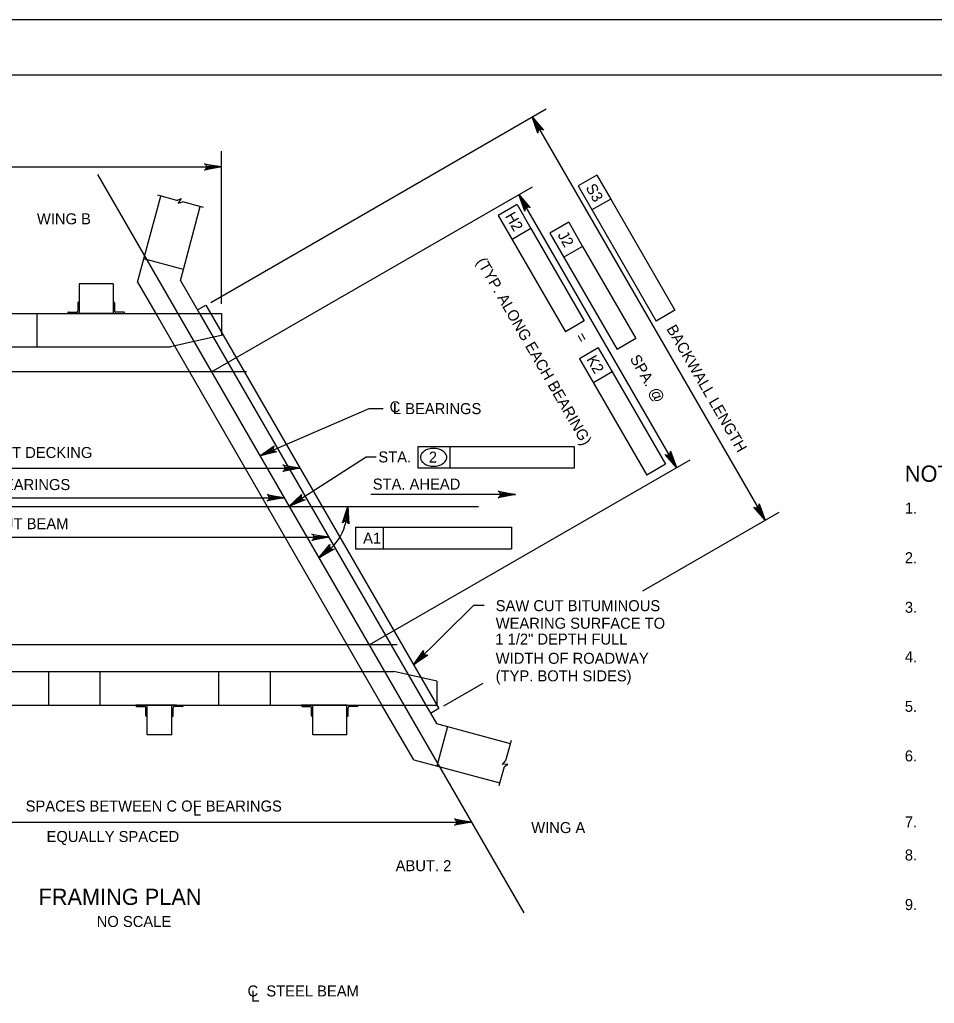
# Model space of a CAD drawing. Extents: x 638175 to 640495, y 294277 to 298435.
# Drawn here: x 639605.4 to 639854.5, y 298167.4 to 298435.5 of the extents above; entities that cross this region are included whole.
import ezdxf

# ---------------------------------------------------------------- set-up
doc = ezdxf.new("R2010")
doc.units = 0
for name, color, linetype in [('2', 7, 'Continuous'), ('3', 7, 'Continuous'), ('4', 7, 'Continuous'), ('PLT-BNDY', 7, 'Continuous')]:
    doc.layers.add(name, color=color, linetype=linetype)

msp = doc.modelspace()

# ---------------------------------------------------------------- linework, layer by layer
at = {"layer": '2'}
for p, q in [((639316.46, 298420.46), (640102.46, 298420.46)), ((639637.52, 298363.97), (639643.8, 298387.4)), ((639650.02, 298367.43), (639654.59, 298384.51)), ((639650.02, 298367.43), (639639.22, 298370.32)), ((639649.21, 298364.4), (639650.02, 298367.43)), ((639649.21, 298364.4), (639654.39, 298355.43)), ((639630.84, 298363.52), (639621.6, 298363.52)), ((639621.6, 298363.52), (639621.6, 298355.43)), ((639630.84, 298363.52), (639630.84, 298355.43)), ((639637.52, 298363.97), (639642.46, 298355.43)), ((639621.24, 298358.34), (639621.24, 298356.15)), ((639621.42, 298358.52), (639621.6, 298358.52)), ((639621.6, 298358.52), (639621.6, 298355.43)), ((639631.02, 298358.52), (639630.84, 298358.52)), ((639630.84, 298358.52), (639630.84, 298355.43)), ((639631.2, 298358.34), (639631.2, 298356.15)), ((639653.84, 298356.38), (639656.08, 298357.67)), ((639656.08, 298357.67), (639719.54, 298247.75)), ((639455.72, 298355.43), (639660.35, 298355.43)), ((639610.05, 298355.43), (639610.05, 298346.31)), ((639618.51, 298355.61), (639618.51, 298355.43)), ((639621.6, 298355.43), (639618.51, 298355.43)), ((639618.69, 298355.79), (639620.87, 298355.79)), ((639630.84, 298355.43), (639621.6, 298355.43)), ((639630.84, 298355.43), (639633.93, 298355.43)), ((639633.75, 298355.79), (639631.56, 298355.79)), ((639633.93, 298355.61), (639633.93, 298355.43)), ((639642.46, 298355.43), (639704.07, 298248.7)), ((639654.39, 298355.43), (639716.01, 298248.7)), ((639660.35, 298355.43), (639660.35, 298349.4)), ((639658.17, 298348.91), (639646.49, 298346.31)), ((639660.34, 298349.4), (639658.17, 298348.91)), ((639469.57, 298346.31), (639646.49, 298346.31)), ((639561.51, 298257.82), (639707.31, 298257.82)), ((639613.3, 298248.7), (639613.3, 298257.82)), ((639627.32, 298248.7), (639627.32, 298257.82)), ((639659.66, 298248.7), (639659.66, 298257.82)), ((639673.68, 298248.7), (639673.68, 298257.82)), ((639718.99, 298255.22), (639707.31, 298257.82)), ((639718.99, 298255.22), (639718.99, 298248.7)), ((639514.35, 298248.7), (639718.99, 298248.7)), ((639637.04, 298248.52), (639637.04, 298248.7)), ((639640.13, 298248.7), (639637.04, 298248.7)), ((639637.22, 298248.34), (639639.4, 298248.34)), ((639648.11, 298248.7), (639638.87, 298248.7)), ((639639.76, 298245.79), (639639.76, 298247.97)), ((639646.85, 298248.7), (639640.13, 298248.7)), ((639640.13, 298245.61), (639640.13, 298248.7)), ((639640.13, 298240.61), (639640.13, 298248.7)), ((639646.85, 298245.61), (639646.85, 298248.7)), ((639646.85, 298248.7), (639649.94, 298248.7)), ((639646.85, 298240.61), (639646.85, 298248.7)), ((639647.22, 298245.79), (639647.22, 298247.97)), ((639649.76, 298248.34), (639647.58, 298248.34)), ((639649.94, 298248.52), (639649.94, 298248.7)), ((639682.14, 298248.52), (639682.14, 298248.7)), ((639685.24, 298248.7), (639682.14, 298248.7)), ((639682.33, 298248.34), (639684.51, 298248.34)), ((639684.87, 298245.79), (639684.87, 298247.97)), ((639694.47, 298248.7), (639685.24, 298248.7)), ((639685.24, 298245.61), (639685.24, 298248.7)), ((639685.24, 298240.61), (639685.24, 298248.7)), ((639694.47, 298245.61), (639694.47, 298248.7)), ((639694.47, 298248.7), (639697.56, 298248.7)), ((639694.47, 298240.61), (639694.47, 298248.7)), ((639694.84, 298245.79), (639694.84, 298247.97)), ((639697.38, 298248.34), (639695.2, 298248.34)), ((639697.56, 298248.52), (639697.56, 298248.7)), ((639712.7, 298233.75), (639704.07, 298248.7)), ((639716.01, 298248.7), (639718.92, 298243.66)), ((639719.54, 298247.75), (639717.3, 298246.45)), ((639639.94, 298245.61), (639640.13, 298245.61)), ((639647.04, 298245.61), (639646.85, 298245.61)), ((639685.05, 298245.61), (639685.24, 298245.61)), ((639694.65, 298245.61), (639694.47, 298245.61)), ((639718.92, 298243.66), (639721.94, 298242.85)), ((639721.94, 298242.85), (639719.05, 298232.05)), ((639721.94, 298242.85), (639739.02, 298238.27)), ((639646.85, 298240.61), (639640.13, 298240.61)), ((639694.47, 298240.61), (639685.24, 298240.61)), ((639712.7, 298233.75), (639736.13, 298227.48))]:
    msp.add_line(p, q, dxfattribs=at)
for centre, radius, start, end in [((639621.42, 298358.34), 0.182, 90, 179.9984), ((639631.02, 298358.34), 0.182, 0.0016, 90), ((639618.69, 298355.61), 0.182, 90, 179.9984), ((639620.87, 298356.15), 0.364, 270, 359.9984), ((639631.56, 298356.15), 0.364, 180.0016, 270), ((639633.75, 298355.61), 0.182, 0.0016, 90), ((639637.22, 298248.52), 0.182, 180.0016, 270), ((639639.4, 298247.97), 0.364, 0.0016, 90), ((639647.58, 298247.97), 0.364, 90, 179.9984), ((639649.76, 298248.52), 0.182, 270, 359.9984), ((639682.33, 298248.52), 0.182, 180.0016, 270), ((639684.51, 298247.97), 0.364, 0.0016, 90), ((639695.2, 298247.97), 0.364, 90, 179.9984), ((639697.38, 298248.52), 0.182, 270, 359.9984), ((639639.94, 298245.79), 0.182, 180.0016, 270), ((639647.04, 298245.79), 0.182, 270, 359.9984), ((639685.05, 298245.79), 0.182, 180.0016, 270), ((639694.65, 298245.79), 0.182, 270, 359.9984)]:
    msp.add_arc(centre, radius, start, end, dxfattribs=at)
at = {"layer": '3'}
for p, q in [((639626.58, 298393.25), (639742.7, 298192.14)), ((639648.16, 298386.23), (639643.04, 298387.6)), ((639648.16, 298386.23), (639649.37, 298386.75)), ((639649.37, 298386.75), (639648.54, 298385.5)), ((639648.54, 298385.5), (639649.83, 298385.79)), ((639655.43, 298384.29), (639649.83, 298385.79)), ((639739.25, 298239.1), (639737.75, 298233.5)), ((639736.86, 298232.53), (639737.75, 298233.5)), ((639737.3, 298231.84), (639735.93, 298226.71)), ((639738.35, 298232.62), (639736.86, 298232.53)), ((639737.3, 298231.84), (639738.35, 298232.62))]:
    msp.add_line(p, q, dxfattribs=at)
at = {"layer": '4'}
for p, q in [((639657.41, 298358.44), (639748.77, 298411.19)), ((639744.93, 298408.97), (639808.4, 298299.05)), ((639660.35, 298358.07), (639660.35, 298399.6)), ((639455.72, 298395.34), (639660.35, 298395.34)), ((639762.59, 298393.12), (639757.48, 298390.17)), ((639762.59, 298393.12), (639766.37, 298386.57)), ((639657.64, 298339.46), (639745.03, 298389.91)), ((639757.48, 298390.17), (639778.74, 298353.34)), ((639784.26, 298313.42), (639741.37, 298387.79)), ((639766.37, 298386.57), (639761.26, 298383.62)), ((639766.37, 298386.57), (639783.85, 298356.3)), ((639740.84, 298385.07), (639735.72, 298382.11)), ((639740.84, 298385.07), (639744.62, 298378.52)), ((639735.72, 298382.11), (639754.01, 298350.44)), ((639744.62, 298378.52), (639739.5, 298375.57)), ((639744.62, 298378.52), (639759.12, 298353.39)), ((639754.94, 298380.24), (639749.82, 298377.29)), ((639754.94, 298380.24), (639758.72, 298373.69)), ((639749.82, 298377.29), (639768.11, 298345.61)), ((639758.72, 298373.69), (639753.6, 298370.74)), ((639758.72, 298373.69), (639773.23, 298348.56)), ((639783.85, 298356.3), (639778.74, 298353.34)), ((639759.12, 298353.39), (639754.01, 298350.44)), ((639773.23, 298348.56), (639768.11, 298345.61)), ((639762.99, 298346.02), (639757.88, 298343.07)), ((639762.99, 298346.02), (639766.77, 298339.47)), ((639757.88, 298343.07), (639776.17, 298311.39)), ((639667.19, 298339.46), (639366.77, 298339.46)), ((639766.77, 298339.47), (639761.66, 298336.52)), ((639766.77, 298339.47), (639781.28, 298314.35)), ((639670.8, 298316.66), (639700.55, 298329.47)), ((639700.55, 298329.47), (639704.41, 298329.47)), ((639713.9, 298313.27), (639713.9, 298319.18)), ((639713.9, 298319.18), (639722.65, 298319.18)), ((639722.65, 298313.27), (639722.65, 298319.18)), ((639722.65, 298319.18), (639756.42, 298319.18)), ((639756.42, 298319.18), (639756.42, 298313.27)), ((639678.74, 298302.81), (639699.76, 298316.33)), ((639699.76, 298316.33), (639702.5, 298316.33)), ((639700.57, 298265.1), (639787.96, 298315.56)), ((639781.28, 298314.35), (639776.17, 298311.39)), ((639480.07, 298313.25), (639681.72, 298313.25)), ((639756.42, 298313.27), (639713.9, 298313.27)), ((639740.41, 298306.08), (639701.04, 298306.08)), ((639428.79, 298302.82), (639730.34, 298302.82)), ((639493.67, 298305.2), (639677.42, 298305.2)), ((639775.12, 298279.83), (639812.23, 298301.26)), ((639696.82, 298297.15), (639704.38, 298297.15)), ((639696.82, 298297.15), (639696.82, 298291.25)), ((639704.38, 298297.15), (639704.38, 298291.25)), ((639704.38, 298297.15), (639739.34, 298297.15)), ((639739.34, 298297.15), (639739.34, 298291.25)), ((639493.93, 298294.42), (639689.61, 298294.42)), ((639696.82, 298291.25), (639739.34, 298291.25)), ((639712.64, 298259.7), (639729.1, 298275.89)), ((639729.1, 298275.89), (639731.93, 298275.89)), ((639708.19, 298265.1), (639366.47, 298265.1)), ((639720.87, 298248.52), (639731.61, 298254.71)), ((639544.7, 298216.82), (639728.45, 298216.82))]:
    msp.add_line(p, q, dxfattribs=at)
for points in [[(639746.83, 298406.66), (639745.98, 298406.17), (639744.93, 298408.97)], [(639742.37, 298385.1), (639743.19, 298385.57), (639741.37, 298387.79)], [(639782.44, 298315.64), (639783.25, 298316.11), (639784.26, 298313.42)], [(639807.35, 298301.85), (639806.49, 298301.36), (639808.4, 298299.05)], [(639715.34, 298261.7), (639714.68, 298262.37), (639712.99, 298260.05)]]:
    msp.add_lwpolyline(points, close=True, dxfattribs=at)
for points in [[(639744.93, 298408.97), (639748.02, 298405.37), (639747.62, 298405.56), (639747.26, 298405.57), (639746.96, 298405.46), (639746.72, 298405.25), (639746.54, 298404.94), (639746.5, 298404.5), (639744.93, 298408.97), (639746.54, 298404.94), (639746.72, 298405.25), (639744.93, 298408.97), (639746.96, 298405.46), (639747.26, 298405.57), (639744.93, 298408.97), (639747.62, 298405.56)], [(639660.35, 298395.34), (639655.69, 298394.46), (639656.05, 298394.71), (639656.24, 298395.02), (639656.29, 298395.34), (639656.24, 298395.65), (639656.05, 298395.96), (639655.69, 298396.21), (639660.35, 298395.34), (639656.05, 298395.96), (639656.24, 298395.65), (639660.35, 298395.34), (639656.29, 298395.34), (639656.24, 298395.02), (639660.35, 298395.34), (639656.05, 298394.71)], [(639741.37, 298387.79), (639744.45, 298384.19), (639744.05, 298384.38), (639743.69, 298384.38), (639743.39, 298384.27), (639743.15, 298384.07), (639742.97, 298383.76), (639742.94, 298383.32), (639741.37, 298387.79), (639742.97, 298383.76), (639743.15, 298384.07), (639741.37, 298387.79), (639743.39, 298384.27), (639743.69, 298384.38), (639741.37, 298387.79), (639744.05, 298384.38)], [(639670.8, 298316.66), (639674.74, 298319.31), (639674.51, 298318.94), (639674.46, 298318.58), (639674.53, 298318.27), (639674.71, 298318), (639675, 298317.79), (639675.43, 298317.7), (639670.8, 298316.66), (639675, 298317.79), (639674.71, 298318), (639670.8, 298316.66), (639674.53, 298318.27), (639674.46, 298318.58), (639670.8, 298316.66), (639674.51, 298318.94)], [(639784.26, 298313.42), (639781.18, 298317.02), (639781.57, 298316.83), (639781.93, 298316.83), (639782.23, 298316.94), (639782.48, 298317.14), (639782.65, 298317.46), (639782.69, 298317.89), (639784.26, 298313.42), (639782.65, 298317.46), (639782.48, 298317.14), (639784.26, 298313.42), (639782.23, 298316.94), (639781.93, 298316.83), (639784.26, 298313.42), (639781.57, 298316.83)], [(639681.72, 298313.25), (639677.06, 298312.38), (639677.42, 298312.63), (639677.6, 298312.94), (639677.66, 298313.25), (639677.6, 298313.57), (639677.42, 298313.88), (639677.06, 298314.13), (639681.72, 298313.25), (639677.42, 298313.88), (639677.6, 298313.57), (639681.72, 298313.25), (639677.66, 298313.25), (639677.6, 298312.94), (639681.72, 298313.25), (639677.42, 298312.63)], [(639677.42, 298305.2), (639672.76, 298304.33), (639673.12, 298304.57), (639673.3, 298304.89), (639673.36, 298305.2), (639673.3, 298305.51), (639673.12, 298305.82), (639672.76, 298306.07), (639677.42, 298305.2), (639673.12, 298305.82), (639673.3, 298305.51), (639677.42, 298305.2), (639673.36, 298305.2), (639673.3, 298304.89), (639677.42, 298305.2), (639673.12, 298304.57)], [(639678.74, 298302.81), (639682.18, 298306.06), (639682.02, 298305.66), (639682.03, 298305.3), (639682.15, 298305), (639682.37, 298304.77), (639682.69, 298304.61), (639683.13, 298304.59), (639678.74, 298302.81), (639682.69, 298304.61), (639682.37, 298304.77), (639678.74, 298302.81), (639682.15, 298305), (639682.03, 298305.3), (639678.74, 298302.81), (639682.02, 298305.66)], [(639740.41, 298306.08), (639735.75, 298305.21), (639736.11, 298305.46), (639736.3, 298305.77), (639736.35, 298306.08), (639736.3, 298306.4), (639736.11, 298306.71), (639735.75, 298306.96), (639740.41, 298306.08), (639736.11, 298306.71), (639736.3, 298306.4), (639740.41, 298306.08), (639736.35, 298306.08), (639736.3, 298305.77), (639740.41, 298306.08), (639736.11, 298305.46)], [(639694.75, 298302.82), (639695, 298298.09), (639694.81, 298298.47), (639694.52, 298298.7), (639694.22, 298298.79), (639693.9, 298298.78), (639693.57, 298298.64), (639693.27, 298298.32), (639694.75, 298302.82), (639693.57, 298298.64), (639693.9, 298298.78), (639694.75, 298302.82), (639694.22, 298298.79), (639694.52, 298298.7), (639694.75, 298302.82), (639694.81, 298298.47)], [(639808.4, 298299.05), (639805.31, 298302.65), (639805.7, 298302.46), (639806.07, 298302.45), (639806.37, 298302.56), (639806.61, 298302.77), (639806.79, 298303.08), (639806.82, 298303.52), (639808.4, 298299.05), (639806.79, 298303.08), (639806.61, 298302.77), (639808.4, 298299.05), (639806.37, 298302.56), (639806.07, 298302.45), (639808.4, 298299.05), (639805.7, 298302.46)], [(639689.61, 298294.42), (639684.95, 298293.55), (639685.31, 298293.8), (639685.5, 298294.11), (639685.55, 298294.42), (639685.5, 298294.73), (639685.31, 298295.05), (639684.95, 298295.29), (639689.61, 298294.42), (639685.31, 298295.05), (639685.5, 298294.73), (639689.61, 298294.42), (639685.55, 298294.42), (639685.5, 298294.11), (639689.61, 298294.42), (639685.31, 298293.8)], [(639686.88, 298288.82), (639689.88, 298292.49), (639689.77, 298292.07), (639689.83, 298291.71), (639689.99, 298291.44), (639690.23, 298291.23), (639690.57, 298291.11), (639691.01, 298291.15), (639686.88, 298288.82), (639690.57, 298291.11), (639690.23, 298291.23), (639686.88, 298288.82), (639689.99, 298291.44), (639689.83, 298291.71), (639686.88, 298288.82), (639689.77, 298292.07)], [(639712.64, 298259.7), (639715.35, 298263.59), (639715.27, 298263.16), (639715.35, 298262.81), (639715.54, 298262.55), (639715.79, 298262.37), (639716.14, 298262.27), (639716.58, 298262.35), (639712.64, 298259.7), (639716.14, 298262.27), (639715.79, 298262.37), (639712.64, 298259.7), (639715.54, 298262.55), (639715.35, 298262.81), (639712.64, 298259.7), (639715.27, 298263.16)], [(639728.45, 298216.82), (639723.79, 298215.95), (639724.15, 298216.19), (639724.33, 298216.51), (639724.39, 298216.82), (639724.33, 298217.13), (639724.15, 298217.44), (639723.79, 298217.69), (639728.45, 298216.82), (639724.15, 298217.44), (639724.33, 298217.13), (639728.45, 298216.82), (639724.39, 298216.82), (639724.33, 298216.51), (639728.45, 298216.82), (639724.15, 298216.19)]]:
    msp.add_lwpolyline(points, dxfattribs=at)
for centre, radius, start, end in [((639716.23, 298316.21), 1.68, 148.5507, 180), ((639716.23, 298316.21), 1.68, 180, 211.4493), ((639717.14, 298315.65), 2.75, 124.109, 148.5507), ((639717.74, 298314.77), 3.82, 105.6708, 124.109), ((639718.13, 298313.37), 5.27, 90, 105.6708), ((639718.13, 298313.37), 5.27, 74.3292, 90), ((639718.53, 298314.77), 3.82, 55.891, 74.3292), ((639719.13, 298315.65), 2.75, 31.4493, 55.891), ((639720.04, 298316.21), 1.68, 0, 31.4493), ((639720.04, 298316.21), 1.68, 328.5507, 0), ((639717.14, 298316.77), 2.75, 211.4493, 235.891), ((639717.74, 298317.66), 3.82, 235.891, 254.3292), ((639718.13, 298319.06), 5.27, 254.3292, 270), ((639718.13, 298319.06), 5.27, 270, 285.6708), ((639718.53, 298317.66), 3.82, 285.6708, 304.109), ((639719.13, 298316.77), 2.75, 304.109, 328.5507), ((639678.99, 298302.48), 15.77, 299.9997, 1.2352)]:
    msp.add_arc(centre, radius, start, end, dxfattribs=at)
at = {"layer": 'PLT-BNDY'}
msp.add_lwpolyline([(639276.46, 298435.46), (640117.46, 298435.46), (640117.46, 297841.46), (639276.46, 297841.46)], close=True, dxfattribs=at)

# ---------------------------------------------------------------- texts
at = {"layer": '4'}
for s, height, rotation, p in [('S3', 3, 299.9382, (639759.43, 298389.7)), ('H2', 3, 299.9382, (639737.5, 298381.94)), ('J2', 3, 299.9382, (639751.78, 298376.81)), ('(TYP. ALONG EACH BEARING)', 3, 299.9745, (639729.68, 298369.57)), ('BACKWALL LENGTH', 3, 299.9745, (639781.44, 298351.25)), ('= ', 2.953, 299.9745, (639756.63, 298349.15)), ('K2', 3, 299.9382, (639759.64, 298342.93)), ('SPA. @', 3, 299.9745, (639771.47, 298343.12)), ('A1', 3, 359.9382, (639698.94, 298292.7))]:
    msp.add_text(s, height=height, rotation=rotation, dxfattribs=at).set_placement(p)
for s, height, p in [('WING B', 3, (639610.09, 298379.7)), ('C', 3.02, (639706.15, 298328.45)), ('L BEARINGS', 3, (639707.05, 298327.98)), ('OUT TO OUT DECKING', 3, (639581.05, 298316.02)), ('STA.', 3, (639703.08, 298314.82)), ('2', 3, (639716.83, 298314.76)), ('NOTES:', 4.429, (639846.47, 298309.55)), ('C/C BEARINGS', 3, (639590.41, 298307.29)), ('STA. AHEAD', 3, (639701.55, 298307.42)), ('1.', 3, (639846.47, 298300.86)), ('OUT TO OUT BEAM', 3, (639581.46, 298296.63)), ('2.', 3, (639846.47, 298287.36)), ('SAW CUT BITUMINOUS', 3, (639735.04, 298274.29)), ('3.', 3, (639846.47, 298273.86)), ('WEARING SURFACE TO ', 3, (639735.04, 298269.51)), ('1 1/2" DEPTH FULL', 3, (639734.94, 298265.18)), ('WIDTH OF ROADWAY', 3, (639735.04, 298259.95)), ('4.', 3, (639846.47, 298260.36)), ('(TYP. BOTH SIDES)', 3, (639735.04, 298255.17)), ('5.', 3, (639846.47, 298246.86)), ('6.', 3, (639846.47, 298233.36)), ('SPACES BETWEEN C OF BEARINGS', 3, (639607.02, 298219.7)), ('L', 3, (639652.63, 298218.57)), ('7.', 3, (639846.47, 298215.36)), ('EQUALLY SPACED', 3, (639612.72, 298211.4)), ('WING A', 3, (639744.72, 298213.83)), ('8.', 3, (639846.47, 298206.36)), ('ABUT. 2', 3, (639707.8, 298203.45)), ('FRAMING PLAN', 4.4292, (639610.51, 298194.25)), ('9.', 3, (639846.47, 298192.86)), ('NO SCALE', 3, (639626.37, 298188.25)), ('C  STEEL BEAM', 3, (639667.45, 298169.32)), ('L', 3, (639668.43, 298167.91))]:
    msp.add_text(s, height=height, dxfattribs=at).set_placement(p)

doc.saveas('drawing.dxf')
